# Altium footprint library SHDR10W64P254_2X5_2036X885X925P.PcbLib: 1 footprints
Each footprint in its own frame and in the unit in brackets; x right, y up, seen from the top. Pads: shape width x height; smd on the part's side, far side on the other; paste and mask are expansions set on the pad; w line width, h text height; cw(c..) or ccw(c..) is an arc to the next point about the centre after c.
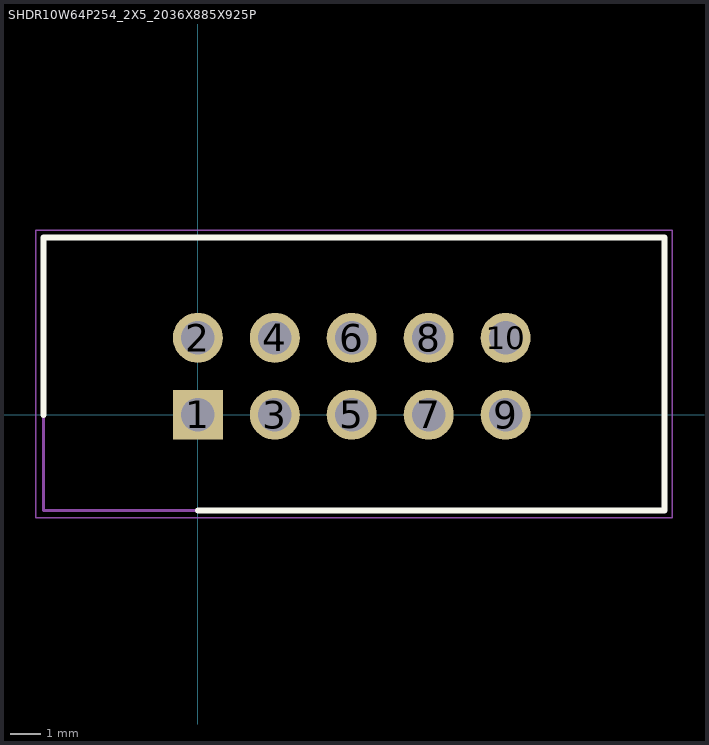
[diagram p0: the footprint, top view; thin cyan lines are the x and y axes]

## SHDR10W64P254_2X5_2036X885X925P [mm]
pads (10):
  rect 1.65x1.65 / inner round 1.65 / far side rect 1.65x1.65 hole 1.1: 1(0,0)
  round 1.65 hole 1.1: 2(0,2.54) 3(2.54,0) 4(2.54,2.54) 5(5.08,0) 6(5.08,2.54) 7(7.62,0) 8(7.62,2.54) 9(10.16,0) 10(10.16,2.54)
Top Overlay:
  lines w0.2: -5.1,0 -5.1,5.845 15.41,5.845 15.41,-3.155 0,-3.155
Mechanical 15:
  lines w0.1: -5.1,-3.155 -5.1,5.845 15.41,5.845 15.41,-3.155 -5.1,-3.155
Mechanical 20:
  lines w0.05: -5.35,-3.405 -5.35,6.095 15.66,6.095 15.66,-3.405 -5.35,-3.405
